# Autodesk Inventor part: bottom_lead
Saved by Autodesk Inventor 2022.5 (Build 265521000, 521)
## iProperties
Created: 2024-12
Part Number: bottom_lead
Material: Generic
Document SubType Name: Modeling
Designer: AdminForWorker
Density: 1 g/cm^3
Appearance: Default
Title: bottom_lead
Author: AdminForWorker
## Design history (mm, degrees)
feature "Body1"
body "Solid1"
